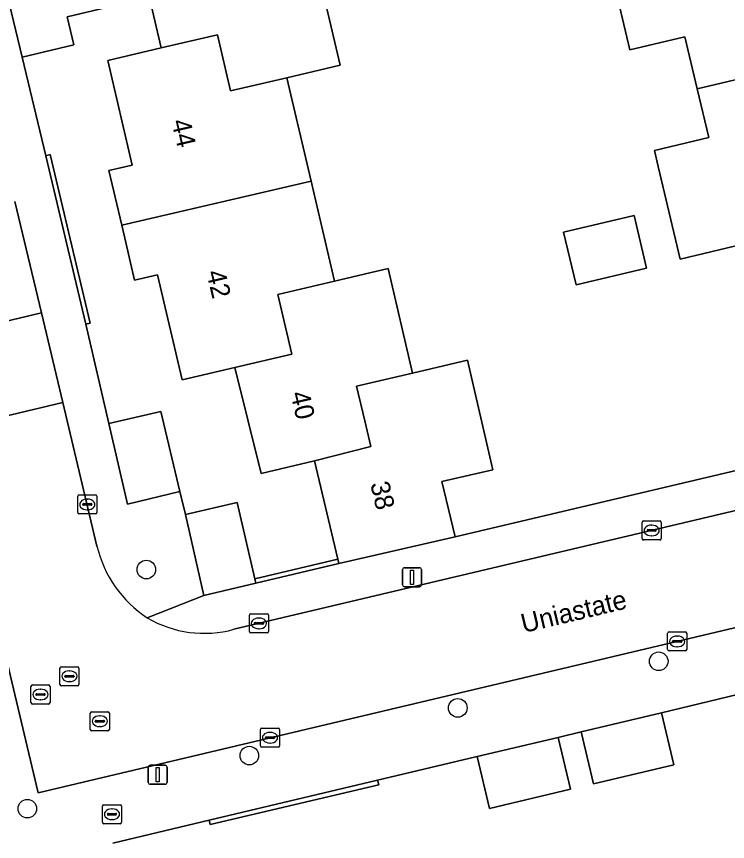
# Model space of a CAD drawing. Extents: x 158031 to 159244, y 380104 to 381214.
# Drawn here: x 158521.15 to 158558.47, y 380477.91 to 380521.24 of the extents above; entities that cross this region are included whole.
import ezdxf

# ---------------------------------------------------------------- set-up
doc = ezdxf.new("R2010")
doc.units = 0
for name, color, linetype in [('IMGEO_Boom', 7, 'Continuous'), ('IMGEO_Brandkraan', 7, 'Continuous'), ('IMGEO_Erf', 7, 'Continuous'), ('IMGEO_Hek', 7, 'Continuous'), ('IMGEO_Kolk', 7, 'Continuous'), ('IMGEO_Lichtmast', 7, 'Continuous'), ('IMGEO_Muur', 7, 'Continuous'), ('IMGEO_Openbare_ruimte_label', 7, 'Continuous'), ('IMGEO_Pand', 7, 'Continuous'), ('IMGEO_Pand_nummerreeks', 7, 'Continuous'), ('IMGEO_Rijbaan_lokaal_open', 7, 'Continuous'), ('IMGEO_Rioolput', 7, 'Continuous'), ('IMGEO_Voetpad_open', 7, 'Continuous')]:
    doc.layers.add(name, color=color, linetype=linetype)

msp = doc.modelspace()

# ---------------------------------------------------------------- linework, layer by layer
at = {"layer": 'IMGEO_Boom'}
for centre in [(158527.962, 380492.194), (158554.86, 380487.377), (158544.31, 380484.93), (158533.368, 380482.426), (158521.715, 380479.639)]:
    msp.add_circle(centre, 0.489, dxfattribs=at)
at = {"layer": 'IMGEO_Brandkraan'}
for p, q in [((158525.658, 380478.921), (158525.658, 380479.773)), ((158525.733, 380479.847), (158526.585, 380479.847)), ((158526.146, 380479.627), (158526.171, 380479.627)), ((158526.659, 380479.773), (158526.659, 380478.921)), ((158525.917, 380479.341), (158525.917, 380479.353)), ((158526.355, 380479.304), (158525.957, 380479.304)), ((158525.96, 380479.39), (158526.358, 380479.39)), ((158526.169, 380479.067), (158526.144, 380479.067)), ((158526.401, 380479.353), (158526.401, 380479.341)), ((158526.585, 380478.847), (158525.733, 380478.847))]:
    msp.add_line(p, q, dxfattribs=at)
for points in [[(158525.658, 380478.921), (158525.658, 380479.773)], [(158525.733, 380479.847), (158526.585, 380479.847)], [(158526.659, 380479.773), (158526.659, 380478.921)], [(158526.585, 380478.847), (158525.733, 380478.847)]]:
    msp.add_lwpolyline(points, dxfattribs=at)
for centre, radius, start, end in [((158525.735, 380479.771), 0.0765, 91.552, 178.448), ((158525.735, 380479.771), 0.0765, 91.552, 178.448), ((158526.583, 380479.771), 0.0765, 1.552, 88.448), ((158526.583, 380479.771), 0.0765, 1.552, 88.448), ((158525.957, 380479.35), 0.0403, 85.8775, 175.7526), ((158525.954, 380479.34), 0.0366, 178.938, 274.7102), ((158526.358, 380479.347), 0.043, 264.8664, 352.4533), ((158526.362, 380479.352), 0.0386, 1.7309, 96.639), ((158525.735, 380478.923), 0.0765, 181.552, 268.448), ((158525.735, 380478.923), 0.0765, 181.552, 268.448), ((158526.583, 380478.923), 0.0765, 271.552, 358.448), ((158526.583, 380478.923), 0.0765, 271.552, 358.448)]:
    msp.add_arc(centre, radius, start, end, dxfattribs=at)
for centre, major_axis, ratio, start_param, end_param in [((158526.145, 380479.347), (-0.387, 0.002), 0.722429, 4.712389, 7.853982), ((158526.17, 380479.347), (-0.39, 0.002), 0.717154, 1.570796, 4.712389)]:
    msp.add_ellipse(centre, major_axis=major_axis, ratio=ratio, start_param=start_param, end_param=end_param, dxfattribs=at)
at = {"layer": 'IMGEO_Erf'}
for points in [[(158558.839, 380509.174), (158555.981, 380508.498), (158554.83, 380513.364), (158554.63, 380514.207), (158557.489, 380514.883), (158556.885, 380517.432), (158556.238, 380520.165), (158553.35, 380519.481), (158552.017, 380525.115), (158554.949, 380525.809), (158553.656, 380531.271), (158556.494, 380531.943), (158555.223, 380537.31), (158565.254, 380539.731)], [(158525.808, 380521.699), (158523.81, 380521.227), (158524.16, 380519.742), (158521.435, 380519.099), (158522.685, 380513.928), (158522.916, 380513.983), (158525.018, 380505.127), (158524.787, 380505.072), (158525.995, 380499.864), (158528.723, 380500.496), (158529.725, 380496.291), (158530.009, 380495.078), (158532.737, 380495.708), (158533.659, 380491.711), (158538.013, 380492.741), (158536.787, 380497.91), (158533.982, 380497.245), (158532.616, 380502.81), (158529.839, 380502.16), (158528.547, 380507.679), (158527.345, 380507.398), (158526.672, 380510.272), (158525.999, 380513.144), (158527.223, 380513.431), (158525.935, 380518.932), (158528.747, 380519.591), (158527.463, 380525.075)], [(158536.865, 380524.125), (158538.141, 380518.679), (158535.336, 380518.022), (158536.607, 380512.597), (158537.837, 380507.343), (158540.649, 380508.002), (158541.934, 380502.513), (158544.817, 380503.188), (158546.158, 380497.437), (158543.482, 380496.81), (158544.171, 380493.905), (158564.336, 380498.667)], [(158565.881, 380487.297), (158555.012, 380484.672), (158555.66, 380481.948), (158551.433, 380480.943), (158550.786, 380483.667), (158549.578, 380483.382), (158550.223, 380480.657), (158545.976, 380479.653), (158545.332, 380482.377), (158540.105, 380481.127), (158540.159, 380480.898), (158531.321, 380478.806), (158531.267, 380479.035), (158526.205, 380477.822)]]:
    msp.add_lwpolyline(points, dxfattribs=at)
msp.add_lwpolyline([(158553.565, 380510.793), (158554.221, 380508.019), (158550.52, 380507.144), (158549.863, 380509.918)], close=True, dxfattribs=at)
at = {"layer": 'IMGEO_Hek'}
for points in [[(158564.336, 380498.667), (158544.171, 380493.905)], [(158565.881, 380487.297), (158555.012, 380484.672)]]:
    msp.add_lwpolyline(points, dxfattribs=at)
at = {"layer": 'IMGEO_Kolk'}
for p, q in [((158524.363, 380495.188), (158524.363, 380496.04)), ((158524.438, 380496.114), (158525.29, 380496.114)), ((158525.364, 380496.04), (158525.364, 380495.188)), ((158524.622, 380495.608), (158524.622, 380495.62)), ((158525.06, 380495.571), (158524.662, 380495.571)), ((158524.665, 380495.657), (158525.063, 380495.657)), ((158524.851, 380495.894), (158524.876, 380495.894)), ((158525.106, 380495.62), (158525.106, 380495.608)), ((158525.29, 380495.114), (158524.438, 380495.114)), ((158524.874, 380495.334), (158524.849, 380495.334)), ((158553.987, 380493.821), (158553.987, 380494.673)), ((158554.062, 380494.747), (158554.914, 380494.747)), ((158554.988, 380494.673), (158554.988, 380493.821)), ((158554.246, 380494.241), (158554.246, 380494.253)), ((158554.684, 380494.204), (158554.286, 380494.204)), ((158554.289, 380494.29), (158554.687, 380494.29)), ((158554.475, 380494.527), (158554.5, 380494.527)), ((158554.73, 380494.253), (158554.73, 380494.241)), ((158554.498, 380493.967), (158554.473, 380493.967)), ((158554.914, 380493.747), (158554.062, 380493.747)), ((158533.447, 380489.868), (158534.299, 380489.868)), ((158533.372, 380488.942), (158533.372, 380489.794)), ((158533.86, 380489.648), (158533.885, 380489.648)), ((158534.373, 380489.794), (158534.373, 380488.942)), ((158533.631, 380489.362), (158533.631, 380489.374)), ((158534.069, 380489.325), (158533.671, 380489.325)), ((158533.674, 380489.411), (158534.072, 380489.411)), ((158533.883, 380489.088), (158533.858, 380489.088)), ((158534.115, 380489.374), (158534.115, 380489.362)), ((158534.299, 380488.868), (158533.447, 380488.868)), ((158555.328, 380487.995), (158555.328, 380488.847)), ((158555.403, 380488.921), (158556.255, 380488.921)), ((158555.816, 380488.701), (158555.841, 380488.701)), ((158556.329, 380488.847), (158556.329, 380487.995)), ((158555.587, 380488.415), (158555.587, 380488.427)), ((158556.025, 380488.378), (158555.627, 380488.378)), ((158555.63, 380488.464), (158556.028, 380488.464)), ((158555.839, 380488.141), (158555.814, 380488.141)), ((158556.071, 380488.427), (158556.071, 380488.415)), ((158556.255, 380487.921), (158555.403, 380487.921)), ((158533.953, 380482.938), (158533.953, 380483.79)), ((158534.028, 380483.864), (158534.88, 380483.864)), ((158534.954, 380483.79), (158534.954, 380482.938)), ((158534.212, 380483.358), (158534.212, 380483.37)), ((158534.255, 380483.407), (158534.653, 380483.407)), ((158534.441, 380483.644), (158534.466, 380483.644)), ((158534.696, 380483.37), (158534.696, 380483.358)), ((158534.65, 380483.321), (158534.252, 380483.321)), ((158534.464, 380483.084), (158534.439, 380483.084)), ((158534.88, 380482.864), (158534.028, 380482.864))]:
    msp.add_line(p, q, dxfattribs=at)
for points in [[(158524.363, 380495.188), (158524.363, 380496.04)], [(158524.438, 380496.114), (158525.29, 380496.114)], [(158525.364, 380496.04), (158525.364, 380495.188)], [(158525.29, 380495.114), (158524.438, 380495.114)], [(158553.987, 380493.821), (158553.987, 380494.673)], [(158554.062, 380494.747), (158554.914, 380494.747)], [(158554.988, 380494.673), (158554.988, 380493.821)], [(158554.914, 380493.747), (158554.062, 380493.747)], [(158533.447, 380489.868), (158534.299, 380489.868)], [(158533.372, 380488.942), (158533.372, 380489.794)], [(158534.373, 380489.794), (158534.373, 380488.942)], [(158534.299, 380488.868), (158533.447, 380488.868)], [(158555.328, 380487.995), (158555.328, 380488.847)], [(158555.403, 380488.921), (158556.255, 380488.921)], [(158556.329, 380488.847), (158556.329, 380487.995)], [(158556.255, 380487.921), (158555.403, 380487.921)], [(158533.953, 380482.938), (158533.953, 380483.79)], [(158534.028, 380483.864), (158534.88, 380483.864)], [(158534.954, 380483.79), (158534.954, 380482.938)], [(158534.88, 380482.864), (158534.028, 380482.864)]]:
    msp.add_lwpolyline(points, dxfattribs=at)
for centre, radius, start, end in [((158524.44, 380496.038), 0.0765, 91.552, 178.448), ((158524.44, 380496.038), 0.0765, 91.552, 178.448), ((158525.288, 380496.038), 0.0765, 1.552, 88.448), ((158525.288, 380496.038), 0.0765, 1.552, 88.448), ((158524.662, 380495.617), 0.0403, 85.8775, 175.7526), ((158524.659, 380495.607), 0.0366, 178.938, 274.7102), ((158525.063, 380495.614), 0.043, 264.8664, 352.4533), ((158525.067, 380495.619), 0.0386, 1.7309, 96.639), ((158524.44, 380495.19), 0.0765, 181.552, 268.448), ((158524.44, 380495.19), 0.0765, 181.552, 268.448), ((158525.288, 380495.19), 0.0765, 271.552, 358.448), ((158525.288, 380495.19), 0.0765, 271.552, 358.448), ((158554.064, 380494.671), 0.0765, 91.552, 178.448), ((158554.064, 380494.671), 0.0765, 91.552, 178.448), ((158554.912, 380494.671), 0.0765, 1.552, 88.448), ((158554.912, 380494.671), 0.0765, 1.552, 88.448), ((158554.286, 380494.25), 0.0403, 85.8775, 175.7526), ((158554.283, 380494.24), 0.0366, 178.938, 274.7102), ((158554.687, 380494.247), 0.043, 264.8664, 352.4533), ((158554.691, 380494.252), 0.0386, 1.7309, 96.639), ((158554.064, 380493.823), 0.0765, 181.552, 268.448), ((158554.064, 380493.823), 0.0765, 181.552, 268.448), ((158554.912, 380493.823), 0.0765, 271.552, 358.448), ((158554.912, 380493.823), 0.0765, 271.552, 358.448), ((158533.449, 380489.792), 0.0765, 91.552, 178.448), ((158533.449, 380489.792), 0.0765, 91.552, 178.448), ((158534.297, 380489.792), 0.0765, 1.552, 88.448), ((158534.297, 380489.792), 0.0765, 1.552, 88.448), ((158533.671, 380489.371), 0.0403, 85.8775, 175.7526), ((158533.668, 380489.361), 0.0366, 178.938, 274.7102), ((158534.072, 380489.368), 0.043, 264.8664, 352.4533), ((158534.076, 380489.373), 0.0386, 1.7309, 96.639), ((158533.449, 380488.944), 0.0765, 181.552, 268.448), ((158533.449, 380488.944), 0.0765, 181.552, 268.448), ((158534.297, 380488.944), 0.0765, 271.552, 358.448), ((158534.297, 380488.944), 0.0765, 271.552, 358.448), ((158555.405, 380488.845), 0.0765, 91.552, 178.448), ((158555.405, 380488.845), 0.0765, 91.552, 178.448), ((158556.253, 380488.845), 0.0765, 1.552, 88.448), ((158556.253, 380488.845), 0.0765, 1.552, 88.448), ((158555.627, 380488.424), 0.0403, 85.8775, 175.7526), ((158555.624, 380488.414), 0.0366, 178.938, 274.7102), ((158556.028, 380488.421), 0.043, 264.8664, 352.4533), ((158556.032, 380488.426), 0.0386, 1.7309, 96.639), ((158555.405, 380487.997), 0.0765, 181.552, 268.448), ((158555.405, 380487.997), 0.0765, 181.552, 268.448), ((158556.253, 380487.997), 0.0765, 271.552, 358.448), ((158556.253, 380487.997), 0.0765, 271.552, 358.448), ((158534.03, 380483.788), 0.0765, 91.552, 178.448), ((158534.03, 380483.788), 0.0765, 91.552, 178.448), ((158534.878, 380483.788), 0.0765, 1.552, 88.448), ((158534.878, 380483.788), 0.0765, 1.552, 88.448), ((158534.252, 380483.367), 0.0403, 85.8775, 175.7526), ((158534.249, 380483.357), 0.0366, 178.938, 274.7102), ((158534.653, 380483.364), 0.043, 264.8664, 352.4533), ((158534.657, 380483.369), 0.0386, 1.7309, 96.639), ((158534.03, 380482.94), 0.0765, 181.552, 268.448), ((158534.03, 380482.94), 0.0765, 181.552, 268.448), ((158534.878, 380482.94), 0.0765, 271.552, 358.448), ((158534.878, 380482.94), 0.0765, 271.552, 358.448)]:
    msp.add_arc(centre, radius, start, end, dxfattribs=at)
for centre, major_axis, ratio, start_param, end_param in [((158524.85, 380495.614), (-0.387, 0.002), 0.722429, 4.712389, 7.853982), ((158524.875, 380495.614), (-0.39, 0.002), 0.717154, 1.570796, 4.712389), ((158554.474, 380494.247), (-0.387, 0.002), 0.722429, 4.712389, 7.853982), ((158554.499, 380494.247), (-0.39, 0.002), 0.717154, 1.570796, 4.712389), ((158533.859, 380489.368), (-0.387, 0.002), 0.722429, 4.712389, 7.853982), ((158533.884, 380489.368), (-0.39, 0.002), 0.717154, 1.570796, 4.712389), ((158555.815, 380488.421), (-0.387, 0.002), 0.722429, 4.712389, 7.853982), ((158555.84, 380488.421), (-0.39, 0.002), 0.717154, 1.570796, 4.712389), ((158534.44, 380483.364), (-0.387, 0.002), 0.722429, 4.712389, 7.853982), ((158534.465, 380483.364), (-0.39, 0.002), 0.717154, 1.570796, 4.712389)]:
    msp.add_ellipse(centre, major_axis=major_axis, ratio=ratio, start_param=start_param, end_param=end_param, dxfattribs=at)
at = {"layer": 'IMGEO_Lichtmast'}
for p, q in [((158541.41, 380491.392), (158541.41, 380492.192)), ((158541.41, 380492.192), (158541.41, 380491.392)), ((158541.51, 380492.292), (158542.3, 380492.292)), ((158542.3, 380492.292), (158541.51, 380492.292)), ((158542.4, 380492.192), (158542.4, 380491.392)), ((158542.4, 380491.392), (158542.4, 380492.192)), ((158542.3, 380491.292), (158541.51, 380491.292)), ((158541.51, 380491.292), (158542.3, 380491.292)), ((158528.064, 380481.021), (158528.064, 380481.821)), ((158528.064, 380481.821), (158528.064, 380481.021)), ((158528.164, 380481.921), (158528.954, 380481.921)), ((158528.954, 380481.921), (158528.164, 380481.921)), ((158529.054, 380481.821), (158529.054, 380481.021)), ((158529.054, 380481.021), (158529.054, 380481.821)), ((158528.954, 380480.921), (158528.164, 380480.921)), ((158528.164, 380480.921), (158528.954, 380480.921))]:
    msp.add_line(p, q, dxfattribs=at)
for points in [[(158541.83, 380492.167), (158541.98, 380492.167), (158541.98, 380491.417), (158541.83, 380491.417), (158541.83, 380492.167)], [(158528.484, 380481.796), (158528.634, 380481.796), (158528.634, 380481.046), (158528.484, 380481.046), (158528.484, 380481.796)]]:
    msp.add_lwpolyline(points, dxfattribs=at)
for centre, start, end in [((158541.51, 380492.192), 90, 180), ((158541.51, 380492.192), 90, 180), ((158542.3, 380492.192), 0, 90), ((158542.3, 380492.192), 360, 90), ((158541.51, 380491.392), 180, 270), ((158541.51, 380491.392), 180, 270), ((158542.3, 380491.392), 270, 0), ((158542.3, 380491.392), 270, 0), ((158528.164, 380481.821), 90, 180), ((158528.164, 380481.821), 90, 180), ((158528.954, 380481.821), 0, 90), ((158528.954, 380481.821), 360, 90), ((158528.164, 380481.021), 180, 270), ((158528.164, 380481.021), 180, 270), ((158528.954, 380481.021), 270, 0), ((158528.954, 380481.021), 270, 0)]:
    msp.add_arc(centre, 0.1, start, end, dxfattribs=at)
at = {"layer": 'IMGEO_Muur'}
for points in [[(158525.018, 380505.127), (158522.916, 380513.983), (158522.685, 380513.928), (158524.787, 380505.072)], [(158533.713, 380491.477), (158538.069, 380492.508), (158538.013, 380492.741), (158533.659, 380491.711)], [(158531.267, 380479.035), (158531.321, 380478.806), (158540.159, 380480.898), (158540.105, 380481.127)]]:
    msp.add_lwpolyline(points, close=True, dxfattribs=at)
at = {"layer": 'IMGEO_Pand'}
for points in [[(158530.289, 380525.737), (158527.463, 380525.075), (158528.747, 380519.591), (158531.696, 380520.282), (158532.387, 380517.331), (158535.336, 380518.022), (158538.141, 380518.679), (158536.865, 380524.125), (158533.926, 380523.437), (158533.227, 380526.425)], [(158561.465, 380524.154), (158558.565, 380523.468), (158557.849, 380526.495), (158554.949, 380525.809), (158552.017, 380525.115), (158553.35, 380519.481), (158556.238, 380520.165), (158556.885, 380517.432), (158562.725, 380518.83)], [(158523.162, 380523.973), (158520.437, 380523.33), (158521.435, 380519.099), (158524.16, 380519.742), (158523.81, 380521.227), (158525.808, 380521.699), (158525.16, 380524.444)], [(158535.336, 380518.022), (158532.387, 380517.331), (158531.696, 380520.282), (158528.747, 380519.591), (158525.935, 380518.932), (158527.223, 380513.431), (158525.999, 380513.144), (158526.672, 380510.272), (158536.607, 380512.597)], [(158563.985, 380513.504), (158562.725, 380518.83), (158556.885, 380517.432), (158557.489, 380514.883), (158554.63, 380514.207), (158554.83, 380513.364), (158555.981, 380508.498), (158558.839, 380509.174), (158561.761, 380509.865), (158561.063, 380512.812)], [(158537.837, 380507.343), (158536.607, 380512.597), (158526.672, 380510.272), (158527.345, 380507.398), (158528.547, 380507.679), (158529.839, 380502.16), (158532.616, 380502.81), (158535.594, 380503.507), (158534.858, 380506.645)], [(158549.863, 380509.918), (158550.52, 380507.144), (158554.221, 380508.019), (158553.565, 380510.793)], [(158537.837, 380507.343), (158534.858, 380506.645), (158535.594, 380503.507), (158532.616, 380502.81), (158533.982, 380497.245), (158536.787, 380497.91), (158539.738, 380498.664), (158539.425, 380500), (158538.998, 380501.826), (158541.934, 380502.513), (158540.649, 380508.002)], [(158541.934, 380502.513), (158538.998, 380501.826), (158539.425, 380500), (158539.738, 380498.664), (158536.787, 380497.91), (158538.013, 380492.741), (158538.069, 380492.508), (158544.171, 380493.905), (158543.482, 380496.81), (158546.158, 380497.437), (158544.817, 380503.188)], [(158529.725, 380496.291), (158528.723, 380500.496), (158525.995, 380499.864), (158526.974, 380495.636)], [(158533.713, 380491.477), (158533.659, 380491.711), (158532.737, 380495.708), (158530.009, 380495.078), (158530.987, 380490.837)], [(158550.786, 380483.667), (158551.433, 380480.943), (158555.66, 380481.948), (158555.012, 380484.672)], [(158549.578, 380483.382), (158545.332, 380482.377), (158545.976, 380479.653), (158550.223, 380480.657)]]:
    msp.add_lwpolyline(points, close=True, dxfattribs=at)
at = {"layer": 'IMGEO_Rijbaan_lokaal_open'}
for points in [[(158515.149, 380510.563), (158516.649, 380504.3), (158522.462, 380505.674), (158521.067, 380511.522)], [(158525.367, 380493.429), (158523.58, 380500.961), (158517.767, 380499.583), (158520.895, 380486.296), (158522.276, 380480.47), (158566.227, 380490.892), (158564.893, 380496.712), (158532.563, 380489.056)]]:
    msp.add_lwpolyline(points, dxfattribs=at)
msp.add_lwpolyline([(158523.58, 380500.961), (158522.462, 380505.674), (158516.649, 380504.3), (158517.767, 380499.583)], close=True, dxfattribs=at)
for centre, radius, start, end in [((158531.49, 380494.908), 6.299, 193.5777, 236.4206), ((158530.999, 380494.745), 5.9, 239.5238, 285.3759)]:
    msp.add_arc(centre, radius, start, end, dxfattribs=at)
at = {"layer": 'IMGEO_Rioolput'}
for p, q in [((158523.425, 380486.165), (158523.425, 380487.017)), ((158523.5, 380487.091), (158524.352, 380487.091)), ((158523.913, 380486.871), (158523.938, 380486.871)), ((158524.426, 380487.017), (158524.426, 380486.165)), ((158523.684, 380486.585), (158523.684, 380486.597)), ((158524.122, 380486.548), (158523.724, 380486.548)), ((158523.727, 380486.634), (158524.125, 380486.634)), ((158524.168, 380486.597), (158524.168, 380486.585)), ((158521.904, 380485.207), (158521.904, 380486.059)), ((158521.979, 380486.133), (158522.831, 380486.133)), ((158522.905, 380486.059), (158522.905, 380485.207)), ((158524.352, 380486.091), (158523.5, 380486.091)), ((158523.936, 380486.311), (158523.911, 380486.311)), ((158522.163, 380485.627), (158522.163, 380485.639)), ((158522.601, 380485.59), (158522.203, 380485.59)), ((158522.206, 380485.676), (158522.604, 380485.676)), ((158522.392, 380485.913), (158522.417, 380485.913)), ((158522.647, 380485.639), (158522.647, 380485.627)), ((158522.831, 380485.133), (158521.979, 380485.133)), ((158522.415, 380485.353), (158522.39, 380485.353)), ((158525.021, 380483.803), (158525.021, 380484.655)), ((158525.096, 380484.729), (158525.948, 380484.729)), ((158526.022, 380484.655), (158526.022, 380483.803)), ((158525.28, 380484.223), (158525.28, 380484.235)), ((158525.323, 380484.272), (158525.721, 380484.272)), ((158525.509, 380484.509), (158525.534, 380484.509)), ((158525.764, 380484.235), (158525.764, 380484.223)), ((158525.718, 380484.186), (158525.32, 380484.186)), ((158525.532, 380483.949), (158525.507, 380483.949)), ((158525.948, 380483.729), (158525.096, 380483.729))]:
    msp.add_line(p, q, dxfattribs=at)
for points in [[(158523.425, 380486.165), (158523.425, 380487.017)], [(158523.5, 380487.091), (158524.352, 380487.091)], [(158524.426, 380487.017), (158524.426, 380486.165)], [(158521.904, 380485.207), (158521.904, 380486.059)], [(158521.979, 380486.133), (158522.831, 380486.133)], [(158522.905, 380486.059), (158522.905, 380485.207)], [(158524.352, 380486.091), (158523.5, 380486.091)], [(158522.831, 380485.133), (158521.979, 380485.133)], [(158525.021, 380483.803), (158525.021, 380484.655)], [(158525.096, 380484.729), (158525.948, 380484.729)], [(158526.022, 380484.655), (158526.022, 380483.803)], [(158525.948, 380483.729), (158525.096, 380483.729)]]:
    msp.add_lwpolyline(points, dxfattribs=at)
for centre, radius, start, end in [((158523.502, 380487.015), 0.0765, 91.552, 178.448), ((158523.502, 380487.015), 0.0765, 91.552, 178.448), ((158524.35, 380487.015), 0.0765, 1.552, 88.448), ((158524.35, 380487.015), 0.0765, 1.552, 88.448), ((158523.724, 380486.594), 0.0403, 85.8775, 175.7526), ((158523.721, 380486.584), 0.0366, 178.938, 274.7102), ((158524.125, 380486.591), 0.043, 264.8664, 352.4533), ((158524.129, 380486.596), 0.0386, 1.7309, 96.639), ((158521.981, 380486.057), 0.0765, 91.552, 178.448), ((158521.981, 380486.057), 0.0765, 91.552, 178.448), ((158522.829, 380486.057), 0.0765, 1.552, 88.448), ((158522.829, 380486.057), 0.0765, 1.552, 88.448), ((158523.502, 380486.167), 0.0765, 181.552, 268.448), ((158523.502, 380486.167), 0.0765, 181.552, 268.448), ((158524.35, 380486.167), 0.0765, 271.552, 358.448), ((158524.35, 380486.167), 0.0765, 271.552, 358.448), ((158522.203, 380485.636), 0.0403, 85.8775, 175.7526), ((158522.2, 380485.626), 0.0366, 178.938, 274.7102), ((158522.604, 380485.633), 0.043, 264.8664, 352.4533), ((158522.608, 380485.638), 0.0386, 1.7309, 96.639), ((158521.981, 380485.209), 0.0765, 181.552, 268.448), ((158521.981, 380485.209), 0.0765, 181.552, 268.448), ((158522.829, 380485.209), 0.0765, 271.552, 358.448), ((158522.829, 380485.209), 0.0765, 271.552, 358.448), ((158525.098, 380484.653), 0.0765, 91.552, 178.448), ((158525.098, 380484.653), 0.0765, 91.552, 178.448), ((158525.946, 380484.653), 0.0765, 1.552, 88.448), ((158525.946, 380484.653), 0.0765, 1.552, 88.448), ((158525.32, 380484.232), 0.0403, 85.8775, 175.7526), ((158525.317, 380484.222), 0.0366, 178.938, 274.7102), ((158525.721, 380484.229), 0.043, 264.8664, 352.4533), ((158525.725, 380484.234), 0.0386, 1.7309, 96.639), ((158525.098, 380483.805), 0.0765, 181.552, 268.448), ((158525.098, 380483.805), 0.0765, 181.552, 268.448), ((158525.946, 380483.805), 0.0765, 271.552, 358.448), ((158525.946, 380483.805), 0.0765, 271.552, 358.448)]:
    msp.add_arc(centre, radius, start, end, dxfattribs=at)
for centre, major_axis, ratio, start_param, end_param in [((158523.912, 380486.591), (-0.387, 0.002), 0.722429, 4.712389, 7.853982), ((158523.937, 380486.591), (-0.39, 0.002), 0.717154, 1.570796, 4.712389), ((158522.391, 380485.633), (-0.387, 0.002), 0.722429, 4.712389, 7.853982), ((158522.416, 380485.633), (-0.39, 0.002), 0.717154, 1.570796, 4.712389), ((158525.508, 380484.229), (-0.387, 0.002), 0.722429, 4.712389, 7.853982), ((158525.533, 380484.229), (-0.39, 0.002), 0.717154, 1.570796, 4.712389)]:
    msp.add_ellipse(centre, major_axis=major_axis, ratio=ratio, start_param=start_param, end_param=end_param, dxfattribs=at)
at = {"layer": 'IMGEO_Voetpad_open'}
for points in [[(158528.006, 380489.66), (158530.987, 380490.837), (158530.009, 380495.078), (158529.725, 380496.291), (158526.974, 380495.636), (158525.995, 380499.864), (158524.787, 380505.072), (158522.685, 380513.928), (158521.435, 380519.099), (158520.437, 380523.33), (158520.153, 380524.548), (158519.177, 380528.665), (158510.501, 380526.599), (158504.905, 380525.354), (158502.758, 380524.694), (158497.176, 380523.356), (158493.811, 380522.549), (158494.422, 380520.018), (158491.676, 380519.36), (158484.368, 380517.635), (158484.381, 380517.581), (158478.3, 380516.138), (158453.311, 380510.219)], [(158521.067, 380511.522), (158522.462, 380505.674), (158523.58, 380500.961), (158525.367, 380493.429)], [(158565.881, 380487.297), (158576.024, 380489.715), (158576.713, 380486.721), (158577.624, 380486.941), (158580.749, 380487.695), (158584.029, 380488.461), (158588.105, 380489.392), (158587.386, 380492.338), (158597.49, 380494.805), (158613.675, 380498.576), (158617.449, 380499.44), (158617.159, 380502.945), (158612.772, 380501.896), (158570.966, 380492.021), (158566.227, 380490.892), (158522.276, 380480.47), (158520.895, 380486.296), (158517.767, 380499.583), (158516.649, 380504.3), (158515.149, 380510.563)], [(158532.563, 380489.056), (158564.893, 380496.712), (158569.608, 380497.828), (158580.936, 380500.512)], [(158564.336, 380498.667), (158544.171, 380493.905), (158538.069, 380492.508), (158533.713, 380491.477), (158530.987, 380490.837), (158528.006, 380489.66)], [(158526.205, 380477.822), (158531.267, 380479.035), (158540.105, 380481.127), (158545.332, 380482.377), (158549.578, 380483.382), (158550.786, 380483.667), (158555.012, 380484.672), (158565.881, 380487.297)]]:
    msp.add_lwpolyline(points, dxfattribs=at)
for centre, radius, start, end in [((158531.49, 380494.908), 6.299, 193.5777, 236.4206), ((158530.999, 380494.745), 5.9, 239.5238, 285.3759)]:
    msp.add_arc(centre, radius, start, end, dxfattribs=at)

# ---------------------------------------------------------------- texts
at = {"layer": 'IMGEO_Openbare_ruimte_label'}
msp.add_text('Uniastate', height=1, rotation=13.4111, dxfattribs=at).set_placement((158547.761, 380488.857))
at = {"layer": 'IMGEO_Pand_nummerreeks'}
for s, rotation, p in [('44', 283.1778, (158529.274, 380515.732)), ('42', 283.1757, (158531.106, 380507.806)), ('40', 283.1016, (158535.521, 380501.446)), ('38', 283.176, (158539.711, 380496.703))]:
    msp.add_text(s, height=1, rotation=rotation, dxfattribs=at).set_placement(p)

doc.saveas('drawing.dxf')
